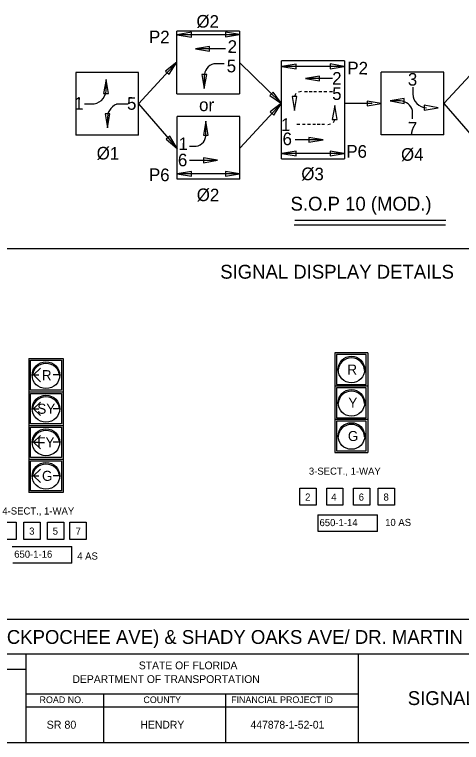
# Model space of a CAD drawing. Extents: x 0 to 1428, y -128 to 567.
# Drawn here: x 0.712 to 1.048, y 0.004 to 0.551 of the extents above; entities that cross this region are included whole.
import ezdxf

# ---------------------------------------------------------------- set-up
doc = ezdxf.new("R2010")
doc.units = 0
for name, color, linetype in [('SheetBorder_dp', 7, 'Continuous'), ('SheetLines_dp', 7, 'Continuous'), ('SignalHead', 7, 'Continuous'), ('TextLabel', 7, 'Continuous'), ('TextMisc', 7, 'Continuous')]:
    doc.layers.add(name, color=color, linetype=linetype)

msp = doc.modelspace()

# ---------------------------------------------------------------- linework, layer by layer
at = {"layer": 'SheetBorder_dp'}
for p, q in [((0.04583311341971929, 0.07083300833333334), (1.3291613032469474, 0.07083300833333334)), ((0.04583311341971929, 0.004166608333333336), (1.3291613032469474, 0.004166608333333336))]:
    msp.add_line(p, q, dxfattribs=at)
at = {"layer": 'SheetLines_dp'}
for p, q in [((0.720830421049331, 0.07083300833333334), (0.720830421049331, 0.004166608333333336)), ((0.9708294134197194, 0.004166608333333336), (0.9708294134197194, 0.07083300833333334)), ((0.5262097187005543, 0.05916638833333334), (0.7208352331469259, 0.05916638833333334)), ((0.720830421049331, 0.04083312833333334), (0.9708294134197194, 0.04083312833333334)), ((0.7791635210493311, 0.04083312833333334), (0.7791635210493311, 0.004166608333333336)), ((0.8708298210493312, 0.04083312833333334), (0.8708298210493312, 0.004166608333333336)), ((0.720830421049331, 0.030833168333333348), (0.9708294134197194, 0.030833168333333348))]:
    msp.add_line(p, q, dxfattribs=at)
at = {"layer": 'SignalHead'}
for p, q in [((0.9780827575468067, 0.29705949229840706), (0.9530928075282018, 0.29705949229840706)), ((0.9530928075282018, 0.29705949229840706), (0.9530928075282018, 0.2220896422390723)), ((0.9768332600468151, 0.29580999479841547), (0.9543423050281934, 0.29580999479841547)), ((0.9543423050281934, 0.29580999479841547), (0.9543423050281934, 0.27331903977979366)), ((0.9768332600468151, 0.27331903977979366), (0.9768332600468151, 0.29580999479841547)), ((0.9780827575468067, 0.29705949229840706), (0.9780827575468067, 0.2220896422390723)), ((0.7230704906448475, 0.2929412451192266), (0.7488934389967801, 0.2929412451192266)), ((0.7230704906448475, 0.2929412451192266), (0.7230704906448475, 0.1920255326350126)), ((0.7243616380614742, 0.2689737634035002), (0.7243616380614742, 0.291679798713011)), ((0.7243616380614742, 0.291679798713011), (0.7476022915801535, 0.291679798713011)), ((0.7476022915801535, 0.291679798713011), (0.7476022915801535, 0.2689737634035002)), ((0.7488934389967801, 0.2929412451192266), (0.7488934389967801, 0.1920255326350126)), ((0.7266180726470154, 0.2804939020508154), (0.7317826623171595, 0.2855396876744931)), ((0.7266180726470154, 0.2804939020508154), (0.7304915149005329, 0.2804939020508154)), ((0.7266180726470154, 0.2804939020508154), (0.7317826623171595, 0.2754481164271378)), ((0.7453458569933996, 0.2804939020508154), (0.7414724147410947, 0.2804939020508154)), ((0.7476022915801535, 0.2689737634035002), (0.7243616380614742, 0.2689737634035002)), ((0.9780827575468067, 0.2720695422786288), (0.9530928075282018, 0.2720695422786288)), ((0.9543423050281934, 0.27331903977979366), (0.9768332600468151, 0.27331903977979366)), ((0.9768332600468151, 0.27082004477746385), (0.9543423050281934, 0.27082004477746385)), ((0.9543423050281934, 0.27082004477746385), (0.9543423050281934, 0.24832908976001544)), ((0.9768332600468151, 0.24832908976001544), (0.9768332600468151, 0.27082004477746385)), ((0.7230704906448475, 0.26771231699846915), (0.7488934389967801, 0.26771231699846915)), ((0.7243616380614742, 0.24374483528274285), (0.7243616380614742, 0.26645087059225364)), ((0.7243616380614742, 0.26645087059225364), (0.7476022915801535, 0.26645087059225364)), ((0.7476022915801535, 0.26645087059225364), (0.7476022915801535, 0.24374483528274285)), ((0.7266180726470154, 0.25509785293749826), (0.7317826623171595, 0.2601436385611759)), ((0.7266180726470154, 0.25509785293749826), (0.7304915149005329, 0.25509785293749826)), ((0.7266180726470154, 0.25509785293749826), (0.7317826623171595, 0.2500520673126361)), ((0.7453458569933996, 0.25509785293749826), (0.7414724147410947, 0.25509785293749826)), ((0.9780827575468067, 0.24707959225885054), (0.9530928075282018, 0.24707959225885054)), ((0.9543423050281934, 0.24832908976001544), (0.9768332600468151, 0.24832908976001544)), ((0.7230704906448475, 0.24248338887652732), (0.7488934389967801, 0.24248338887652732)), ((0.7476022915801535, 0.24374483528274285), (0.7243616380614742, 0.24374483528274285)), ((0.7243616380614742, 0.21851590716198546), (0.7243616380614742, 0.24122194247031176)), ((0.7243616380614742, 0.24122194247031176), (0.7476022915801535, 0.24122194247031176)), ((0.7476022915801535, 0.24122194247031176), (0.7476022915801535, 0.21851590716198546)), ((0.9768332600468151, 0.24583009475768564), (0.9543423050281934, 0.24583009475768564)), ((0.9543423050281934, 0.24583009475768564), (0.9543423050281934, 0.22333913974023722)), ((0.9768332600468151, 0.22333913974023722), (0.9768332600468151, 0.24583009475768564)), ((0.7266180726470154, 0.22986892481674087), (0.7317826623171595, 0.23491471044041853)), ((0.7266180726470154, 0.22986892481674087), (0.7304915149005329, 0.22986892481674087)), ((0.7266180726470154, 0.22986892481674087), (0.7317826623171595, 0.22482313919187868)), ((0.7453458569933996, 0.22986892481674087), (0.7414724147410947, 0.22986892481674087)), ((0.9530928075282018, 0.2220896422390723), (0.9780827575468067, 0.2220896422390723)), ((0.9543423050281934, 0.22333913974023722), (0.9768332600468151, 0.22333913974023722)), ((0.7230704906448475, 0.21725446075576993), (0.7488934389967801, 0.21725446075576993)), ((0.7476022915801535, 0.21851590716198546), (0.7243616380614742, 0.21851590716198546)), ((0.7243616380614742, 0.19328697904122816), (0.7243616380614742, 0.2159930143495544)), ((0.7243616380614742, 0.2159930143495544), (0.7476022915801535, 0.2159930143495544)), ((0.7476022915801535, 0.2159930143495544), (0.7476022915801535, 0.19328697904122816)), ((0.7266180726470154, 0.20466646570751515), (0.7317826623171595, 0.20971225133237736)), ((0.7266180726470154, 0.20466646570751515), (0.7304915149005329, 0.20466646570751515)), ((0.7266180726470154, 0.20466646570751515), (0.7317826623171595, 0.19962068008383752)), ((0.7453458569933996, 0.20466646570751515), (0.7414724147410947, 0.20466646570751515)), ((0.7488934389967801, 0.1920255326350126), (0.7230704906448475, 0.1920255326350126)), ((0.7476022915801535, 0.19328697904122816), (0.7243616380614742, 0.19328697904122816)), ((0.9403982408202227, 0.17537609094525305), (0.98519863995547, 0.17537609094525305)), ((0.9407244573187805, 0.1628811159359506), (0.9407244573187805, 0.17537609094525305)), ((0.98519863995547, 0.1628811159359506), (0.98519863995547, 0.17537609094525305)), ((0.98519863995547, 0.1628811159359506), (0.9407244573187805, 0.1628811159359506)), ((0.7106765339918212, 0.1514130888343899), (0.7554769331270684, 0.1514130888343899)), ((0.7554769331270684, 0.13891811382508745), (0.7554769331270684, 0.1514130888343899)), ((0.7554769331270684, 0.13891811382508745), (0.7110027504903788, 0.13891811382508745))]:
    msp.add_line(p, q, dxfattribs=at)
for centre in [(0.9655877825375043, 0.2845645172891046), (0.9655877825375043, 0.2595745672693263), (0.9655877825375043, 0.23458461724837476)]:
    msp.add_circle(centre, 0.009995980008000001, dxfattribs=at)
for centre in [(0.9655877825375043, 0.28331501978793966), (0.9655877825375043, 0.2583250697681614), (0.9655877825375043, 0.23333511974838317)]:
    msp.add_arc(centre, 0.009995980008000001, 3.5833216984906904, 176.41667830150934, dxfattribs=at)
for centre in [(0.7359819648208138, 0.28032678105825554), (0.7359819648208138, 0.25509785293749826), (0.7359819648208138, 0.22986892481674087), (0.7359819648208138, 0.20463999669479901)]:
    msp.add_ellipse(centre, major_axis=(-0.010329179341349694, 1.2649596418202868e-18), ratio=0.9769964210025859, dxfattribs=at)
for centre in [(0.7359819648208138, 0.2790653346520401), (0.7359819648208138, 0.2538364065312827), (0.7359819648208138, 0.2286074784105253), (0.7359819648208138, 0.203378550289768)]:
    msp.add_ellipse(centre, major_axis=(-0.010329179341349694, 1.2649596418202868e-18), ratio=0.9769964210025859, start_param=3.204133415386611, end_param=6.220644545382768, dxfattribs=at)
at = {"layer": 'TextLabel'}
for p, q in [((0.8343224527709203, 0.4918527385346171), (0.8343224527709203, 0.5389898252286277)), ((0.8814595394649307, 0.5389898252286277), (0.8343224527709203, 0.5389898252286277)), ((0.8814595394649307, 0.5389898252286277), (0.8814595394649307, 0.4918527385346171)), ((0.8814595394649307, 0.5363698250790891), (0.8343224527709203, 0.5363698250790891)), ((0.8710101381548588, 0.5257833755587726), (0.8484516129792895, 0.5257833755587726)), ((0.8056069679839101, 0.4844061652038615), (0.8343224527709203, 0.515578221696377)), ((0.8814626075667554, 0.515422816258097), (0.9131726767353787, 0.48460739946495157)), ((0.9131726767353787, 0.44292808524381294), (0.9131726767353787, 0.5167440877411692)), ((0.9603097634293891, 0.5167440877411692), (0.9131726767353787, 0.5167440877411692)), ((0.9603097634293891, 0.5167440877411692), (0.9603097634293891, 0.44292808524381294)), ((1.0351651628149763, 0.484525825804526), (1.0638100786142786, 0.5156227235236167)), ((0.8699800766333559, 0.5144732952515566), (0.862231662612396, 0.5144732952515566)), ((0.9601749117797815, 0.5124821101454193), (0.9130378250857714, 0.5124821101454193)), ((0.8056069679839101, 0.5079731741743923), (0.7584698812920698, 0.5079731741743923)), ((0.7584698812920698, 0.5079731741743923), (0.7584698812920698, 0.4608360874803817)), ((0.8056069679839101, 0.4608360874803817), (0.8056069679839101, 0.5079731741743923)), ((0.8550158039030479, 0.5049975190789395), (0.8550158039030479, 0.4958841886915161)), ((1.035094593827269, 0.508175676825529), (0.9879575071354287, 0.508175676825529)), ((0.9879575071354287, 0.46103859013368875), (0.9879575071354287, 0.508175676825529)), ((1.035094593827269, 0.46103859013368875), (1.035094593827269, 0.508175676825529)), ((0.7811102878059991, 0.495071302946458), (0.7811102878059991, 0.5026114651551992)), ((0.9513170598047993, 0.503495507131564), (0.9310757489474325, 0.503495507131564)), ((0.7811102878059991, 0.49392378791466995), (0.7811102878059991, 0.495071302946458)), ((0.9304439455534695, 0.4935752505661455), (0.9326510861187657, 0.4935752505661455)), ((0.9338116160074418, 0.4935752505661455), (0.9360187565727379, 0.4935752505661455)), ((0.9372428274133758, 0.4935752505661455), (0.9394499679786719, 0.4935752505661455)), ((0.9411188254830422, 0.4935752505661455), (0.9433259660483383, 0.4935752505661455)), ((0.9449948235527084, 0.4935752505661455), (0.9472019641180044, 0.4935752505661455)), ((0.9491249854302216, 0.4935752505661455), (0.9513321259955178, 0.4935752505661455)), ((1.0118006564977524, 0.4969492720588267), (1.0118006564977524, 0.4917995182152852)), ((0.8343224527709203, 0.4918527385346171), (0.8814595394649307, 0.4918527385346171)), ((0.7648522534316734, 0.4844061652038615), (0.7702395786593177, 0.4844061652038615)), ((0.7978391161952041, 0.4840463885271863), (0.7891107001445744, 0.4840463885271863)), ((0.8056069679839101, 0.4844061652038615), (0.8345525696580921, 0.4508592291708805)), ((0.8818860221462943, 0.45134607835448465), (0.9131726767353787, 0.48477290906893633)), ((0.9812871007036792, 0.48453534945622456), (0.9604465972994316, 0.48453534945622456)), ((1.0025244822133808, 0.4865150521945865), (0.99474668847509, 0.4865150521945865)), ((1.0351651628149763, 0.484525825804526), (1.0640401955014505, 0.45106020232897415)), ((1.0116622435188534, 0.4731087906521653), (1.0116622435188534, 0.4792811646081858)), ((0.7823084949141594, 0.4724465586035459), (0.7823084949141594, 0.4662714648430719)), ((0.881689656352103, 0.4749130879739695), (0.8345525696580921, 0.4749130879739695)), ((0.8345525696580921, 0.42777600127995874), (0.8345525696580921, 0.4749130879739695)), ((0.8561035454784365, 0.46164802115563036), (0.8561035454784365, 0.47127525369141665)), ((0.881689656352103, 0.42777600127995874), (0.881689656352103, 0.4749130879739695)), ((0.9268219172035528, 0.46882671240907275), (0.9246147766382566, 0.46882671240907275)), ((0.9309520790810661, 0.46882671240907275), (0.92874493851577, 0.46882671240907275)), ((0.9348280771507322, 0.46882671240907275), (0.9326209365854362, 0.46882671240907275)), ((0.9387040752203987, 0.46882671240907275), (0.9364969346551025, 0.46882671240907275)), ((0.9421352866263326, 0.46882671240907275), (0.9399281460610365, 0.46882671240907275)), ((0.9455029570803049, 0.46882671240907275), (0.9432958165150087, 0.46882671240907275)), ((0.8056069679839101, 0.4608360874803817), (0.7584698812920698, 0.4608360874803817)), ((1.035094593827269, 0.46103859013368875), (0.9879575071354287, 0.46103859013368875)), ((0.9442660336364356, 0.4573838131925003), (0.923425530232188, 0.4573838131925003)), ((0.8439030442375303, 0.4524157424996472), (0.8488379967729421, 0.4524157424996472)), ((0.9601749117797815, 0.44696524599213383), (0.9130378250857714, 0.44696524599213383)), ((0.8439352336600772, 0.44190743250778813), (0.8648758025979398, 0.44190743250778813)), ((0.9131726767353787, 0.44292808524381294), (0.9603097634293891, 0.44292808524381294)), ((0.8814595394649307, 0.431707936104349), (0.8343224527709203, 0.431707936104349)), ((0.881689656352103, 0.42777600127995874), (0.8345525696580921, 0.42777600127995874)), ((0.9229897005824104, 0.3968598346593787), (1.0367299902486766, 0.3968598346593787)), ((0.9226491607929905, 0.3933975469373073), (1.0363894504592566, 0.3933975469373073))]:
    msp.add_line(p, q, dxfattribs=at)
for points in [[(0.8346872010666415, 0.5363698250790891), (0.845267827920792, 0.5345773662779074), (0.845267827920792, 0.5381622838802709)], [(0.8814207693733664, 0.536443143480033), (0.870840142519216, 0.5382356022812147), (0.870840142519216, 0.5346506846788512)], [(0.8484516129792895, 0.5257833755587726), (0.8590322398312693, 0.5239909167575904), (0.8590322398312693, 0.5275758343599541)], [(0.8343224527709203, 0.515578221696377), (0.8258354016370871, 0.5090106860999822), (0.8284720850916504, 0.5065817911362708)], [(0.9134025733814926, 0.5124821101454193), (0.923983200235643, 0.5106896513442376), (0.923983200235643, 0.5142745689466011)], [(0.9601361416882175, 0.5125554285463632), (0.9495555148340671, 0.5143478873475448), (0.9495555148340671, 0.5107629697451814)], [(0.8550158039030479, 0.4958841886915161), (0.8568082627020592, 0.5064648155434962), (0.8532233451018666, 0.5064648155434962)], [(0.9310757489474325, 0.503495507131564), (0.9416563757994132, 0.5017030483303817), (0.9416563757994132, 0.5052879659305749)], [(0.7811102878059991, 0.5026114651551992), (0.7793178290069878, 0.49203083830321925), (0.7829027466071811, 0.49203083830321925)], [(0.9131726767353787, 0.48460739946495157), (0.9068339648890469, 0.4932666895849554), (0.9043355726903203, 0.4906957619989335)], [(0.9228928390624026, 0.4792694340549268), (0.924685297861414, 0.48985006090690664), (0.9211003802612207, 0.48985006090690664)], [(0.99474668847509, 0.4865150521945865), (1.0053273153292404, 0.48472259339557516), (1.0053273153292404, 0.4883075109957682)], [(0.9131726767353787, 0.48477290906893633), (0.9046337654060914, 0.4782729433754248), (0.9072510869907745, 0.4758231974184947)], [(0.9530540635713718, 0.48313252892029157), (0.9512616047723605, 0.47255190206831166), (0.9548465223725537, 0.47255190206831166)], [(0.9879575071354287, 0.4846086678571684), (0.9773768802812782, 0.4864011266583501), (0.9773768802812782, 0.48281620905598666)], [(1.0308031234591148, 0.48145388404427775), (1.0202224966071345, 0.4832463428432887), (1.0202224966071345, 0.4796614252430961)], [(0.7823084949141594, 0.4662714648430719), (0.7841009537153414, 0.476852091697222), (0.7805160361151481, 0.476852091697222)], [(0.8561035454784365, 0.47127525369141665), (0.8543110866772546, 0.46069462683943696), (0.8578960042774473, 0.46069462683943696)], [(0.8345525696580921, 0.4508592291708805), (0.8289976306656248, 0.4600410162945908), (0.8262834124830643, 0.457699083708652)], [(0.9442660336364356, 0.4573838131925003), (0.933685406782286, 0.4591762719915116), (0.933685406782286, 0.4555913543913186)], [(0.9601361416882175, 0.4470385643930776), (0.9495555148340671, 0.4488310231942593), (0.9495555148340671, 0.4452461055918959)], [(0.8648758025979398, 0.44190743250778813), (0.8542951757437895, 0.4436998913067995), (0.8542951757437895, 0.4401149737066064)], [(0.9134025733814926, 0.44696524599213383), (0.923983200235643, 0.4451727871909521), (0.923983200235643, 0.4487577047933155)], [(0.8346872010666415, 0.431707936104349), (0.845267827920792, 0.42991547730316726), (0.845267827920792, 0.43350039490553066)], [(0.8814207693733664, 0.4317812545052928), (0.870840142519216, 0.4335737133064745), (0.870840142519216, 0.4299887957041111)], [(0.623661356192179, 0.09683564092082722), (1.288807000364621, 0.09683564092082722), (1.288807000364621, 0.3752887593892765), (0.623661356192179, 0.3752887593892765)], [(0.9267961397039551, 0.19542487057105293), (0.9390525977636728, 0.19542487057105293), (0.9390525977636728, 0.18248690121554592), (0.9267961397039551, 0.18248690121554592)], [(0.947021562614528, 0.19542487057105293), (0.9592780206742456, 0.19542487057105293), (0.9592780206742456, 0.18248690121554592), (0.947021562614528, 0.18248690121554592)], [(0.9672469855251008, 0.19542487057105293), (0.9795034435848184, 0.19542487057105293), (0.9795034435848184, 0.18248690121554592), (0.9672469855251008, 0.18248690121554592)], [(0.985732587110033, 0.19542487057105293), (0.9979890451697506, 0.19542487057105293), (0.9979890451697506, 0.18248690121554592), (0.985732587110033, 0.18248690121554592)], [(0.7012860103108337, 0.1698295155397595), (0.7135424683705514, 0.1698295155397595), (0.7135424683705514, 0.15689154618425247), (0.7012860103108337, 0.15689154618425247)], [(0.7193398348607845, 0.1698295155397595), (0.7315962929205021, 0.1698295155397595), (0.7315962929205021, 0.15689154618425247), (0.7193398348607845, 0.15689154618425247)], [(0.7370215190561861, 0.1698295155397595), (0.7492779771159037, 0.1698295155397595), (0.7492779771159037, 0.15689154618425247), (0.7370215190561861, 0.15689154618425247)], [(0.7539327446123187, 0.1698295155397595), (0.7661892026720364, 0.1698295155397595), (0.7661892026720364, 0.15689154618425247), (0.7539327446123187, 0.15689154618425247)]]:
    msp.add_lwpolyline(points, close=True, dxfattribs=at)
for centre, radius, start, end in [((0.8643280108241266, 0.5053915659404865), 0.00932054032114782, 102.99799722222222, 182.42303055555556), ((0.7708958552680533, 0.4946217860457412), 0.0102366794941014, 266.32422777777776, 356.0954777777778), ((0.9283178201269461, 0.4872939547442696), 0.006259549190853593, 92.18896121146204, 112.13544664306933), ((0.9260843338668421, 0.4896455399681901), 0.003198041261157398, 131.4253776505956, 176.33332155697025), ((1.0223172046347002, 0.4919707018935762), 0.010517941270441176, 180.93255277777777, 269.1625007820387), ((0.7926905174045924, 0.4741319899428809), 0.010517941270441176, 109.7362962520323, 189.22103333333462), ((1.0018274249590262, 0.4763021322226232), 0.0102366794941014, 17.219554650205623, 86.09547777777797), ((0.9498625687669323, 0.47275642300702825), 0.003198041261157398, 311.4253776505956, 356.3333215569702), ((0.9476290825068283, 0.47510800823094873), 0.006259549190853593, 272.188961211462, 292.1354466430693), ((0.8475819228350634, 0.4608934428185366), 0.00857024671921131, 278.42775000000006, 5.051219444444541)]:
    msp.add_arc(centre, radius, start, end, dxfattribs=at)

# ---------------------------------------------------------------- texts
at = {"layer": 'SignalHead'}
for s, height, p in [('R', 0.007496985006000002, (0.9625889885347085, 0.2808160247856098)), ('R', 0.0075686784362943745, (0.7328577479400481, 0.27654244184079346)), ('Y', 0.007496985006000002, (0.9633386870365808, 0.2558260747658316)), ('SY', 0.0075686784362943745, (0.7294638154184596, 0.25131351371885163)), ('G', 0.007496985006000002, (0.9629638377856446, 0.23083612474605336)), ('FY', 0.0075686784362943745, (0.7294115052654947, 0.22608458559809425)), ('G', 0.0075686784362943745, (0.732987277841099, 0.20085565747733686)), ('3-SECT., 1-WAY', 0.00534583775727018, (0.9336468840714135, 0.2054983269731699)), ('4-SECT., 1-WAY', 0.00534583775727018, (0.7031748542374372, 0.17555713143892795)), ('  650-1-14  ', 0.00534583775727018, (0.9376690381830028, 0.16681636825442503)), ('10 AS', 0.00534583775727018, (0.9909853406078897, 0.16694518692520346)), ('  650-1-16  ', 0.00534583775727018, (0.708117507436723, 0.14305711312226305)), ('4 AS', 0.00534583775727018, (0.7594856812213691, 0.1416603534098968))]:
    msp.add_text(s, height=height, dxfattribs=at).set_placement(p)
at = {"layer": 'TextLabel'}
for s, p in [('Ø2', (0.8490403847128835, 0.5417605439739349)), ('P2', (0.8133413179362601, 0.5300274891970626)), ('2', (0.8724598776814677, 0.5227447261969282)), ('5', (0.8718093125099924, 0.508088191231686)), ('P2', (0.9624944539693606, 0.5066285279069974)), ('2', (0.9510867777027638, 0.4988276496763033)), ('3', (1.0079942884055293, 0.49809278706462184)), ('5', (0.9510867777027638, 0.48733818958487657)), ('1', (0.7570036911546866, 0.4799545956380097)), ('5', (0.7968468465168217, 0.4799545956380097)), ('or', (0.8510305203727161, 0.47896939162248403)), ('1', (0.912623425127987, 0.4640418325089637)), ('7', (1.0079942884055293, 0.4613700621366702)), ('6', (0.9137877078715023, 0.45335516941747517)), ('1', (0.8356012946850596, 0.44962991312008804)), ('Ø1', (0.774041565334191, 0.4426017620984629)), ('P6', (0.961716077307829, 0.4440253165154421)), ('6', (0.8351133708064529, 0.43746926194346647)), ('P6', (0.8133413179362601, 0.42640136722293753)), ('Ø3', (0.927882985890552, 0.4270624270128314)), ('Ø2', (0.8492705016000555, 0.411290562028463))]:
    msp.add_text(s, height=0.009483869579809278, rotation=359.1182527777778, dxfattribs=at).set_placement(p)
for s, height, p in [('Ø4', 0.009483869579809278, (1.0029341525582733, 0.4415707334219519)), ('S.O.P 10 (MOD.)', 0.010416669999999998, (0.919842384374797, 0.404053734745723)), ('SIGNAL DISPLAY DETAILS', 0.010416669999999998, (0.8669830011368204, 0.35289561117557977)), ('2', 0.00534583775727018, (0.9308194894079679, 0.18600633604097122)), ('4', 0.00534583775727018, (0.9504270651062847, 0.18600633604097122)), ('6', 0.00534583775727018, (0.9710906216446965, 0.18600633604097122)), ('8', 0.00534583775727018, (0.9897509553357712, 0.18600633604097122)), ('3', 0.00534583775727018, (0.7233582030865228, 0.1604109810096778)), ('5', 0.00534583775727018, (0.7410398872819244, 0.1604109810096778)), ('7', 0.00534583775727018, (0.7582848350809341, 0.1604109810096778)), ('SR 80 (W HICKPOCHEE AVE) & SHADY OAKS AVE/ DR. MARTIN LUTHER KING BLVD', 0.010416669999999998, (0.6283981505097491, 0.07826661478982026))]:
    msp.add_text(s, height=height, dxfattribs=at).set_placement(p)
at = {"layer": 'TextMisc'}
for s, height, p in [('STATE OF FLORIDA', 0.005833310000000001, (0.8057777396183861, 0.05917650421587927)), ('DEPARTMENT OF TRANSPORTATION', 0.005833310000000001, (0.7558926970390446, 0.04887711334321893)), ('ROAD NO.', 0.004999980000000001, (0.7311531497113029, 0.03375993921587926)), ('COUNTY', 0.004999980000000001, (0.8092455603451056, 0.03375993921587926)), ('FINANCIAL PROJECT ID', 0.004999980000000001, (0.8751823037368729, 0.033759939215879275)), ('SIGNALIZATION PLAN (3)', 0.010416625, (1.0079906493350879, 0.03229149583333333)), ('SR 80', 0.006, (0.7364758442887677, 0.014499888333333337)), ('HENDRY', 0.0058331, (0.8070089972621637, 0.014583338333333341)), ('447878-1-52-01', 0.0058331, (0.8897653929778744, 0.014583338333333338))]:
    msp.add_text(s, height=height, dxfattribs=at).set_placement(p)

doc.saveas('drawing.dxf')
